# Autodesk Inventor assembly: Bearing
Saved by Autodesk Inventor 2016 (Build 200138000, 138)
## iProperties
Created: 2015-08
Part Number: Bearing
Document SubType Name: Assembly
Designer: Ugljesa
ClientObjectVersion: 1
Author: Ugljesa
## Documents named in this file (2)
- C:\Users\Ugljesa\Desktop\Turbokompr\Assembly1\Design Accelerator\Bearing4.iam
- C:\Users\Ugljesa\Documents\Inventor\Content Center Files\R2016\en-US\BS 292 (V)\BS 292_ Part 1 - N 1005 - 25 x 47 x 12.ipt
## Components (1 placed, 1 different names)
1. BS 292: Part 1 (V) (Metric) N 1005 - 25 x 47 x 12:1
